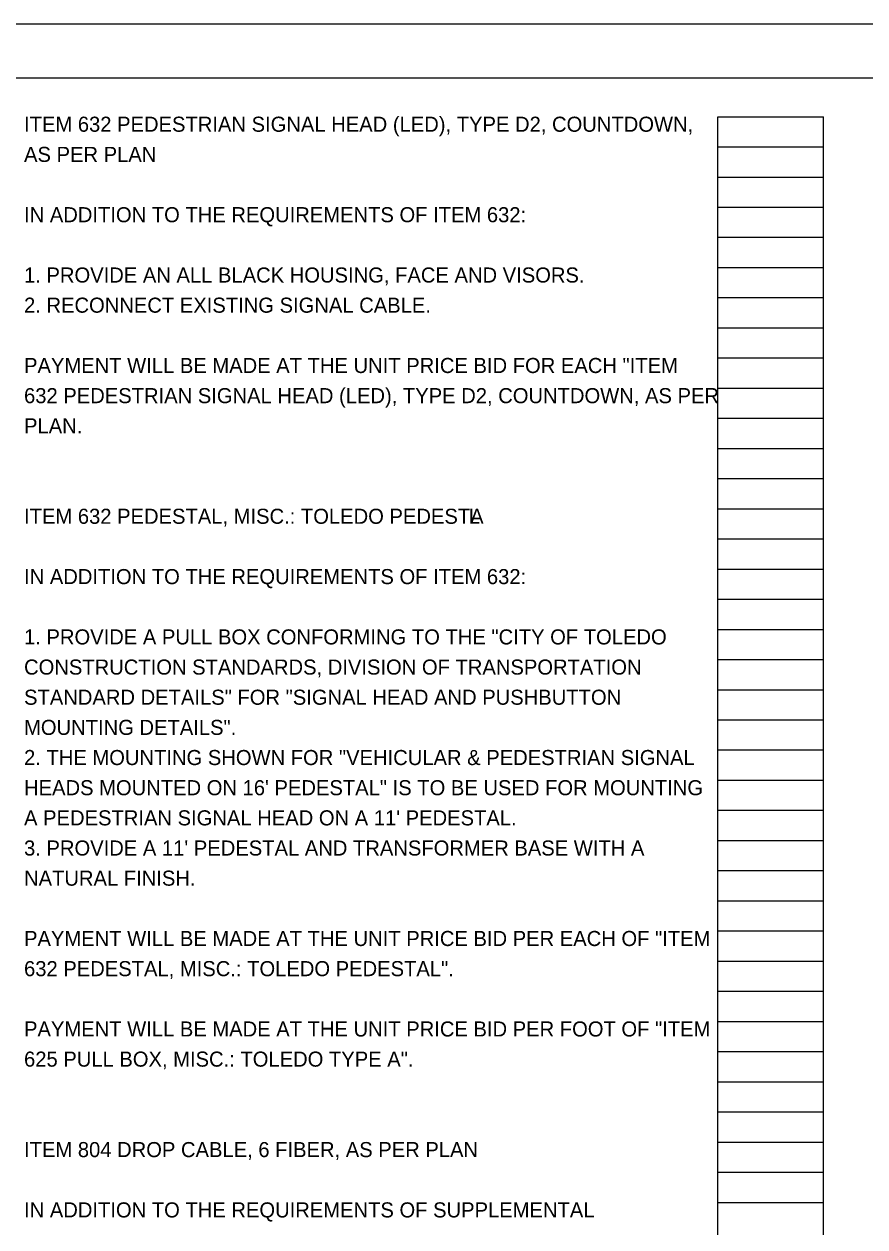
# Model space of a CAD drawing. Extents: x -11.2 to 42.9, y 0 to 22.
# Drawn here: x 17.24 to 25.04, y 10.83 to 22 of the extents above; entities that cross this region are included whole.
import ezdxf

# ---------------------------------------------------------------- set-up
doc = ezdxf.new("R2010")
doc.units = 0
for name, color, linetype in [('SC_Scratch1', 7, 'Continuous'), ('SH_Border', 7, 'Continuous'), ('SH_Cut_Line', 7, 'Continuous'), ('SH_Text', 7, 'Continuous')]:
    doc.layers.add(name, color=color, linetype=linetype)

msp = doc.modelspace()

# ---------------------------------------------------------------- linework, layer by layer
at = {"layer": 'SC_Scratch1'}
for p, q in [((23.68, 0.98), (23.68, 21.14)), ((23.68, 21.14), (24.66, 21.14)), ((24.66, 0.98), (24.66, 21.14)), ((23.68, 20.86), (24.66, 20.86)), ((23.68, 20.58), (24.66, 20.58)), ((23.68, 20.3), (24.66, 20.3)), ((23.68, 20.02), (24.66, 20.02)), ((23.68, 19.74), (24.66, 19.74)), ((23.68, 19.46), (24.66, 19.46)), ((23.68, 19.18), (24.66, 19.18)), ((23.68, 18.9), (24.66, 18.9)), ((23.68, 18.62), (24.66, 18.62)), ((23.68, 18.34), (24.66, 18.34)), ((23.68, 18.06), (24.66, 18.06)), ((23.68, 17.78), (24.66, 17.78)), ((23.68, 17.5), (24.66, 17.5)), ((23.68, 17.22), (24.66, 17.22)), ((23.68, 16.94), (24.66, 16.94)), ((23.68, 16.66), (24.66, 16.66)), ((23.68, 16.38), (24.66, 16.38)), ((23.68, 16.1), (24.66, 16.1)), ((23.68, 15.82), (24.66, 15.82)), ((23.68, 15.54), (24.66, 15.54)), ((23.68, 15.26), (24.66, 15.26)), ((23.68, 14.98), (24.66, 14.98)), ((23.68, 14.7), (24.66, 14.7)), ((23.68, 14.42), (24.66, 14.42)), ((23.68, 14.14), (24.66, 14.14)), ((23.68, 13.86), (24.66, 13.86)), ((23.68, 13.58), (24.66, 13.58)), ((23.68, 13.3), (24.66, 13.3)), ((23.68, 13.02), (24.66, 13.02)), ((23.68, 12.74), (24.66, 12.74)), ((23.68, 12.46), (24.66, 12.46)), ((23.68, 12.18), (24.66, 12.18)), ((23.68, 11.9), (24.66, 11.9)), ((23.68, 11.62), (24.66, 11.62)), ((23.68, 11.34), (24.66, 11.34)), ((23.68, 11.06), (24.66, 11.06))]:
    msp.add_line(p, q, dxfattribs=at)
at = {"layer": 'SH_Border'}
msp.add_lwpolyline([(1.5, 21.5), (33.5, 21.5), (33.5, 0.5), (1.5, 0.5)], close=True, dxfattribs=at)
at = {"layer": 'SH_Cut_Line'}
msp.add_lwpolyline([(0, 0), (34, 0), (34, 22), (0, 22)], close=True, dxfattribs=at)

# ---------------------------------------------------------------- texts
at = {"layer": 'SH_Text'}
for s, p in [('ITEM 632 PEDESTRIAN SIGNAL HEAD (LED), TYPE D2, COUNTDOWN, ', (17.24, 21)), ('AS PER PLAN', (17.24, 20.72)), ('IN ADDITION TO THE REQUIREMENTS OF ITEM 632:', (17.24, 20.16)), ('1. PROVIDE AN ALL BLACK HOUSING, FACE AND VISORS.', (17.24, 19.6)), ('2. RECONNECT EXISTING SIGNAL CABLE.', (17.24, 19.32)), ('PAYMENT WILL BE MADE AT THE UNIT PRICE BID FOR EACH "ITEM ', (17.24, 18.76)), ('632 PEDESTRIAN SIGNAL HEAD (LED), TYPE D2, COUNTDOWN, AS PER ', (17.24, 18.48)), ('PLAN.', (17.24, 18.2)), ('ITEM 632 PEDESTAL, MISC.: TOLEDO PEDESTA', (17.24, 17.36)), ('L', (21.367, 17.36)), ('IN ADDITION TO THE REQUIREMENTS OF ITEM 632:', (17.24, 16.8)), ('1. PROVIDE A PULL BOX CONFORMING TO THE "CITY OF TOLEDO ', (17.24, 16.24)), ('CONSTRUCTION STANDARDS, DIVISION OF TRANSPORTATION ', (17.24, 15.96)), ('STANDARD DETAILS" FOR "SIGNAL HEAD AND PUSHBUTTON ', (17.24, 15.68)), ('MOUNTING DETAILS". ', (17.24, 15.4)), ('2. THE MOUNTING SHOWN FOR "VEHICULAR & PEDESTRIAN SIGNAL ', (17.24, 15.12)), ('HEADS MOUNTED ON 16\' PEDESTAL" IS TO BE USED FOR MOUNTING ', (17.24, 14.84)), ("A PEDESTRIAN SIGNAL HEAD ON A 11' PEDESTAL. ", (17.24, 14.56)), ("3. PROVIDE A 11' PEDESTAL AND TRANSFORMER BASE WITH A ", (17.24, 14.28)), ('NATURAL FINISH.', (17.24, 14)), ('PAYMENT WILL BE MADE AT THE UNIT PRICE BID PER EACH OF "ITEM ', (17.24, 13.44)), ('632 PEDESTAL, MISC.: TOLEDO PEDESTAL".', (17.24, 13.16)), ('PAYMENT WILL BE MADE AT THE UNIT PRICE BID PER FOOT OF "ITEM ', (17.24, 12.6)), ('625 PULL BOX, MISC.: TOLEDO TYPE A".', (17.24, 12.32)), ('ITEM 804 DROP CABLE, 6 FIBER, AS PER PLAN', (17.24, 11.48)), ('IN ADDITION TO THE REQUIREMENTS OF SUPPLEMENTAL ', (17.24, 10.92))]:
    msp.add_text(s, height=0.14, dxfattribs=at).set_placement(p)

doc.saveas('drawing.dxf')
